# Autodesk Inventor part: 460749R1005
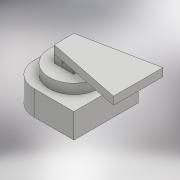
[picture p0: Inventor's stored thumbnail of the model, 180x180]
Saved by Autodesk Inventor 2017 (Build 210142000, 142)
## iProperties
Created: 2016-07
Part Number: 460749R1005
Material: Generic
Document SubType Name: Modeling
Designer: Polytech
Density: 1 g/cm^3
Appearance: Default
Author: Polytech
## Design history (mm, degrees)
sketch "Sketch1"
  geometry: C1 r 23 at (0, 0); 1 further point
  constraints: 1 centre point, 1 coincident
  dimensions: "d0" = 46 diameter of C1
extrude "Extrusion1" new body sketch "Sketch1" distance "d1" = 18; taper "d2" = 0 deg
sketch "Sketch2"
  geometry: L1 (-11.75, -48.75)-(48.75, -48.75); L2 (48.75, -48.75)-(48.75, 48.75); L3 (48.75, 48.75)-(-11.75, 48.75); L4 (-48.75, 11.75)-(-48.75, -11.75); L5 (-48.75, -48.75)-(48.75, 48.75); L6 (48.75, -48.75)-(-48.75, 48.75); A1 r 37 centre (-11.75, 11.75) between (-11.75, 48.75) and (-48.75, 11.75); A2 r 37 centre (-11.75, -11.75) between (-48.75, -11.75) and (-11.75, -48.75); 1 further point
  constraints: 12 end point, 4 point on circle, 4 point on line, 4 tangent, 2 centre point, 2 midpoint, 2 parallel, 1 equal radius, 1 horizontal, 1 perpendicular
  dimensions: "d3" = 97.5 distance of L6.end L2.end; "d4" = 97.5 distance of L2.end L1.end; "d5" = 37 radius of A1
extrude "Extrusion2" join sketch "Sketch2" distance "d6" = 37.5; taper "d7" = 0 deg
sketch "Sketch3"
  geometry: C1 r 37.5 at (0, 0); 1 further point
  constraints: 1 centre point, 1 coincident
  dimensions: "d8" = 75 diameter of C1
extrude "Extrusion3" join sketch "Sketch3" distance "d9" = 15; taper "d10" = 0 deg
sketch "Sketch4"
  geometry: L1 (-15, -15)-(15, -15); L2 (15, -15)-(15, 15); L3 (15, 15)-(-15, 15); L4 (-15, 15)-(-15, -15); L5 (-15, -15)-(15, 15); L6 (15, -15)-(-15, 15); L7 (-15, -6)-(15, -6); L8 (15, -6)-(15, 6); L9 (15, 6)-(-15, 6); L10 (-15, 6)-(-15, -6); L11 (-15, -6)-(15, 6); L12 (15, -6)-(-15, 6); 1 further point
  constraints: 24 end point, 4 midpoint, 4 parallel, 2 horizontal, 2 perpendicular
  dimensions: "d11" = 30 distance of L3.end L2.end; "d12" = 30 distance of L2.end L1.end; "d13" = 30 distance of L9.end L8.end; "d14" = 12 distance of L8.end L7.end
extrude "Extrusion4" join sketch "Sketch4" distance "d15" = 12; taper "d16" = 0 deg
sketch "Sketch5"
  geometry: L1 (52.5, 0)-(-22.5, 0) reference; C1 r 3 at (15, 6); 1 further point
  constraints: 1 centre point, 1 vertical alignment
  dimensions: "d17" = 6 diameter of C1; "d18" = 6 distance from line of L1 C1.centre
extrude "Extrusion5" cut sketch "Sketch5" stored distance "d19" = 12; taper "d20" = 0 deg
sketch "Sketch6"
  geometry: L1 (-15, 15)-(-15, -15); L2 (-15, -15)-(97.5, -37.5); L3 (97.5, -37.5)-(97.5, 37.5); L4 (97.5, 37.5)-(-15, 15); 4 further points
  constraints: 8 end point, 2 coincident, 1 horizontal alignment, 1 midpoint, 1 parallel, 1 vertical
  dimensions: "d21" = 97.5 distance from line of L3 point (0, 0); "d22" = 75 distance of L2.end L3.end
extrude "Extrusion6" join sketch "Sketch6" distance "d23" = 12; taper "d24" = 0 deg
sketch "Sketch7"
  geometry: C1 r 23 at (0, 0); 1 further point
  constraints: 1 centre point, 1 coincident
  dimensions: "d25" = 46 diameter of C1
extrude "Extrusion7" cut sketch "Sketch7" distance "d26" = 24.5; taper "d27" = 0 deg
body "Solid1"
